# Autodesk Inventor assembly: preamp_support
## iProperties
Shininess: 64.0
Length Units: 11272
Angle Units: 11279
Time Units: 11290
Mass Units: 11286
Length Display Precision: 3
Angle Display Precision: 2
Compacted: True
Part Number: preamp_support
Document SubType Name: Assembly
Created: 2004-08
Designer: John Blackburn
Manufacturer: Standard
Standards Organization: Custom
Density: 0.0
Volumn: 0.0
Area: 0.0
PropertySet Name: Model Information
Control State: 0
Master: False
Checked Out: False
Author: John Blackburn
